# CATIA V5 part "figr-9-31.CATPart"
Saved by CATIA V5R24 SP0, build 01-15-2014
Part number: Part1
Bounding box of the stored display mesh (mm): x -60 to 60, y -41.231 to 41.231, z -41.231 to 41.231
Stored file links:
  D:\KAVITA\CATIA V5-6R2014 Project_ Kavita\CATIA V5-6R2014_partfiles\Partfiles\c09_catia_v5-6r2014_prt\figr-9-31.CATPart
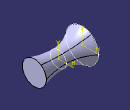
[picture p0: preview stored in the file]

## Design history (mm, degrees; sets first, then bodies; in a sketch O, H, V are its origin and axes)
Body1 (main body)
  Sketch1 on yz-plane, origin (0, 0, 0), H (0, 1, 0), V (0, 0, 1)
    circle A1 centre (0, 0) radius 20
  Plane1: type Offset, RefPlane yz-plane, Offset 60
  Plane2: type Offset, RefPlane yz-plane, Offset -60
  Sketch2 on Plane1, origin (60, 0, 0), H (0, 1, 0), V (0, 0, 1)
    circle A1 centre (0, 0) radius 30
  Sketch3 on Plane2, origin (-60, 0, 0), H (0, 1, 0), V (0, 0, 1)
    circle A1 centre (0, 0) radius 41.2311
  Loft1: solid, Sections (Sketch2; Sketch1; Sketch3)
